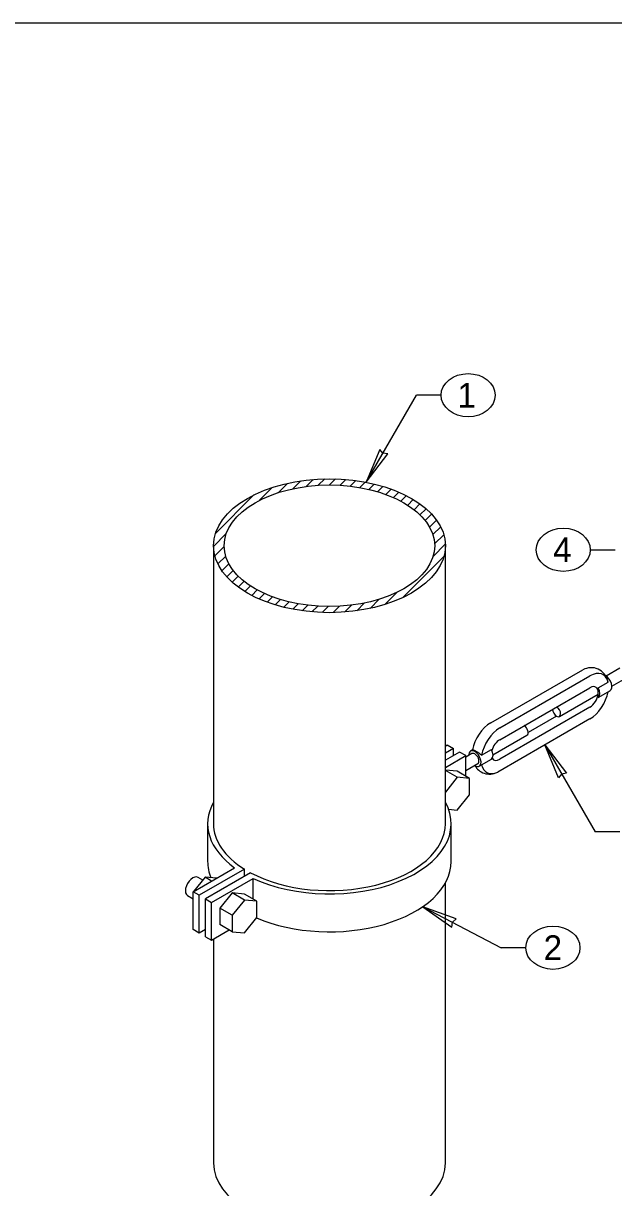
# Model space of a CAD drawing. Extents: x 99862 to 104211, y 98939 to 102076.
# Drawn here: x 101156 to 101538, y 101322 to 102076 of the extents above; entities that cross this region are included whole.
import ezdxf

# ---------------------------------------------------------------- set-up
doc = ezdxf.new("R2010")
doc.units = 0
for name, color, linetype in [('Level 1', 7, 'Continuous'), ('Level 12', 7, 'Continuous'), ('Level 15', 7, 'Continuous'), ('Level 2', 7, 'Continuous'), ('Level 20', 7, 'Continuous'), ('Level 3', 7, 'Continuous')]:
    doc.layers.add(name, color=color, linetype=linetype)

msp = doc.modelspace()

# ---------------------------------------------------------------- linework, layer by layer
at = {"layer": 'Level 1'}
for p, q in [((101279.4, 101737.55), (101279.4, 101557.76)), ((101429.4, 101557.76), (101429.4, 101737.55)), ((101429.4, 101338.36), (101429.4, 101519.41)), ((101279.4, 101483.08), (101279.4, 101338.36))]:
    msp.add_line(p, q, dxfattribs=at)
msp.add_lwpolyline([(99862, 99999.5), (103151, 99999.5), (103151, 102075.5), (99862, 102075.5)], close=True, dxfattribs=at)
for major_axis in [(75, 0), (68.07, 0)]:
    msp.add_ellipse((101354.4, 101737.55), major_axis=major_axis, ratio=0.57735, dxfattribs=at)
msp.add_ellipse((101354.4, 101338.36), major_axis=(75, 0), ratio=0.57735, start_param=3.141593, end_param=6.283185, dxfattribs=at)
at = {"layer": 'Level 12'}
for p, q in [((101309.2, 101766.94), (101317.47, 101775.21)), ((101321.19, 101771.86), (101327.22, 101777.88)), ((101330.83, 101774.42), (101335.92, 101779.51)), ((101339.36, 101775.88), (101343.87, 101780.39)), ((101347.18, 101776.63), (101351.36, 101780.81)), ((101354.47, 101776.85), (101358.39, 101780.77)), ((101361.34, 101776.64), (101365.07, 101780.38)), ((101367.84, 101776.07), (101371.45, 101779.69)), ((101374.02, 101775.18), (101377.55, 101778.72)), ((101379.89, 101773.99), (101383.38, 101777.48)), ((101385.49, 101772.51), (101388.95, 101775.97)), ((101280.73, 101745.54), (101305.61, 101770.41)), ((101390.8, 101770.75), (101394.26, 101774.21)), ((101395.84, 101768.72), (101399.32, 101772.2)), ((101400.6, 101766.41), (101404.12, 101769.93)), ((101405.06, 101763.8), (101408.66, 101767.4)), ((101409.19, 101760.86), (101412.92, 101764.59)), ((101412.97, 101757.57), (101416.89, 101761.49)), ((101416.33, 101753.85), (101420.47, 101757.99)), ((101419.17, 101749.62), (101423.65, 101754.1)), ((101279.42, 101737.16), (101287.72, 101745.45)), ((101421.32, 101744.71), (101426.35, 101749.73)), ((101421.4, 101730.65), (101429.33, 101738.57)), ((101422.43, 101738.74), (101428.34, 101744.65)), ((101280.29, 101730.95), (101286.33, 101737)), ((101282.23, 101725.83), (101287.31, 101730.9)), ((101401.87, 101704.04), (101428.38, 101730.55)), ((101284.86, 101721.38), (101289.38, 101725.91)), ((101288.01, 101717.46), (101292.17, 101721.62)), ((101291.55, 101713.93), (101295.48, 101717.86)), ((101295.47, 101710.78), (101299.22, 101714.53)), ((101299.71, 101707.95), (101303.33, 101711.57)), ((101304.23, 101705.4), (101307.76, 101708.92)), ((101390.33, 101699.57), (101398.26, 101707.5)), ((101309.01, 101703.11), (101312.49, 101706.58)), ((101314.05, 101701.07), (101317.5, 101704.52)), ((101319.33, 101699.29), (101322.79, 101702.74)), ((101324.87, 101697.75), (101328.36, 101701.24)), ((101330.67, 101696.48), (101334.21, 101700.02)), ((101372.11, 101695.49), (101377.12, 101700.51)), ((101380.72, 101697.03), (101386.62, 101702.93)), ((101336.75, 101695.49), (101340.36, 101699.1)), ((101343.1, 101694.77), (101346.83, 101698.49)), ((101349.76, 101694.36), (101353.66, 101698.25)), ((101356.75, 101694.28), (101360.91, 101698.43)), ((101364.19, 101694.64), (101368.67, 101699.13))]:
    msp.add_line(p, q, dxfattribs=at)
at = {"layer": 'Level 15'}
for p, q in [((101378.11, 101778.63), (101410.61, 101834.92)), ((101426.61, 101834.92), (101410.61, 101834.92)), ((101523.11, 101734.94), (101539.11, 101734.94)), ((101493.71, 101608.67), (101526.21, 101552.38)), ((101542.21, 101552.38), (101526.21, 101552.38)), ((101414.71, 101504.04), (101465.43, 101477.54)), ((101481.43, 101477.54), (101465.43, 101477.54))]:
    msp.add_line(p, q, dxfattribs=at)
for points in [[(101378.11, 101778.63), (101392.11, 101796.91), (101389, 101797.49), (101386.94, 101799.89)], [(101493.71, 101608.67), (101507.71, 101590.39), (101504.59, 101589.81), (101502.54, 101587.4)], [(101414.71, 101504.04), (101433.56, 101490.82), (101434.01, 101493.96), (101436.33, 101496.11)]]:
    msp.add_lwpolyline(points, close=True, dxfattribs=at)
at = {"layer": 'Level 2'}
for p, q in [((101429.4, 101607.95), (101430.63, 101608.67)), ((101434.61, 101606.37), (101429.4, 101603.36)), ((101438.59, 101604.08), (101429.4, 101598.77)), ((101430.63, 101608.67), (101434.61, 101606.37)), ((101434.61, 101601.78), (101434.61, 101606.37)), ((101442.56, 101601.78), (101438.59, 101604.08)), ((101429.4, 101594.18), (101442.56, 101601.78)), ((101442.56, 101588.53), (101442.56, 101601.78)), ((101437.1, 101591.68), (101429.4, 101592.37)), ((101437.1, 101587.8), (101429.4, 101592.25)), ((101437.1, 101587.8), (101429.4, 101578.21)), ((101445.05, 101587.09), (101437.1, 101591.68)), ((101445.05, 101587.09), (101437.1, 101587.8)), ((101445.05, 101576.48), (101445.05, 101587.09)), ((101437.1, 101566.58), (101445.05, 101576.48)), ((101431.47, 101567.09), (101437.1, 101566.58)), ((101275.65, 101557.76), (101275.65, 101533.27)), ((101433.15, 101533.27), (101433.15, 101557.76)), ((101266.23, 101513.75), (101293.06, 101529.24)), ((101299.41, 101528.32), (101270.21, 101511.45)), ((101299.41, 101523.72), (101299.41, 101528.32)), ((101273.96, 101523.14), (101266.56, 101513.94)), ((101272.45, 101521.26), (101269.43, 101523)), ((101281.35, 101522.48), (101273.96, 101523.14)), ((101278.23, 101520.68), (101273.96, 101523.14)), ((101303.39, 101526.02), (101274.18, 101509.16)), ((101278.16, 101506.86), (101305, 101522.36)), ((101305, 101509.1), (101305, 101522.36)), ((101266.23, 101489.26), (101266.23, 101513.75)), ((101270.21, 101511.45), (101266.23, 101513.75)), ((101270.21, 101486.96), (101270.21, 101511.45)), ((101291.58, 101512.97), (101283.62, 101503.07)), ((101299.53, 101512.26), (101291.58, 101512.97)), ((101299.53, 101508.37), (101291.58, 101512.97)), ((101307.49, 101507.66), (101299.53, 101512.26)), ((101262.63, 101511.22), (101266.23, 101509.14)), ((101274.18, 101484.66), (101274.18, 101509.16)), ((101274.18, 101509.16), (101278.16, 101506.86)), ((101278.16, 101482.37), (101278.16, 101506.86)), ((101299.53, 101508.37), (101291.58, 101498.48)), ((101307.49, 101507.66), (101299.53, 101508.37)), ((101307.49, 101497.06), (101307.49, 101507.66)), ((101283.62, 101503.07), (101283.62, 101492.46)), ((101291.58, 101498.48), (101283.62, 101503.07)), ((101291.58, 101498.48), (101291.58, 101487.87)), ((101299.53, 101487.16), (101307.49, 101497.06)), ((101270.21, 101486.96), (101266.23, 101489.26)), ((101274.18, 101489.26), (101270.21, 101486.96)), ((101278.16, 101482.37), (101289.64, 101488.99)), ((101291.58, 101487.87), (101283.62, 101492.46)), ((101274.18, 101484.66), (101278.16, 101482.37)), ((101291.58, 101487.87), (101299.53, 101487.16))]:
    msp.add_line(p, q, dxfattribs=at)
for centre, major_axis, start_param, end_param in [((101354.4, 101557.76), (78.75, 0), 2.831748, 3.819642), ((101354.4, 101557.76), (78.75, 0), 4.03434, 6.59303), ((101354.4, 101557.76), (75, 0), 3.141591, 3.889482), ((101354.4, 101557.76), (75, 0), 3.9645, 6.283185), ((101354.4, 101533.27), (78.75, 0), 3.141593, 3.37391), ((101354.4, 101533.27), (78.75, 0), 4.071408, 6.283185), ((101266.03, 101517.11), (-3.4, -5.89), 3.141579, 6.283185)]:
    msp.add_ellipse(centre, major_axis=major_axis, ratio=0.57735, start_param=start_param, end_param=end_param, dxfattribs=at)
at = {"layer": 'Level 20'}
for centre in [(101444.11, 101834.92), (101505.61, 101734.94), (101498.93, 101477.54)]:
    msp.add_ellipse(centre, major_axis=(-17.5, 0), ratio=0.8, dxfattribs=at)
at = {"layer": 'Level 3'}
for p, q in [((101458.7, 101623.02), (101518.34, 101657.37)), ((101542.15, 101658.25), (101533.33, 101653.16)), ((101464.54, 101619.65), (101522.87, 101653.33)), ((101528.27, 101645.66), (101534.62, 101649.32)), ((101537.08, 101646.66), (101544.65, 101651.03)), ((101464.54, 101612.03), (101522.87, 101645.72)), ((101503.17, 101627.08), (101528.26, 101641.57)), ((101528.27, 101643.42), (101528.27, 101645.66)), ((101528.27, 101639.41), (101534.62, 101643.08)), ((101528.27, 101639.41), (101528.27, 101641.65)), ((101534.62, 101643.08), (101535.92, 101643.83)), ((101522.87, 101633.12), (101464.54, 101599.44)), ((101522.87, 101625.51), (101463.22, 101591.15)), ((101501.18, 101627.33), (101482.94, 101616.8)), ((101460.19, 101602.27), (101482.16, 101614.95)), ((101446.59, 101603.08), (101442.56, 101600.75)), ((101447, 101605.48), (101445.65, 101604.7)), ((101452.8, 101602.08), (101459.14, 101605.75)), ((101442.56, 101592.09), (101450.34, 101596.58)), ((101451.28, 101594.96), (101459.14, 101599.5))]:
    msp.add_line(p, q, dxfattribs=at)
for centre, major_axis, start_param, end_param in [((101522.87, 101639.42), (8.52, 14.76), 5.724146, 7.068583), ((101533.11, 101648.7), (-2.81, 4.87), 3.141593, 5.509797), ((101522.87, 101639.42), (-3.86, -6.68), 2.215505, 3.926991), ((101522.87, 101639.42), (8.52, 14.76), 3.926991, 5.271429), ((101522.87, 101639.42), (-3.86, -6.68), 0.785398, 2.215505), ((101525.36, 101644.22), (-2.81, 4.87), 3.179406, 4.674575), ((101501.29, 101630.33), (-1.87, 3.25), 0.828451, 5.454735), ((101458.7, 101609.11), (-8.52, -14.76), 3.926991, 5.271086), ((101464.54, 101605.74), (8.52, 14.76), 0.785398, 2.129836), ((101480.29, 101618.2), (-1.87, 3.25), 3.14158, 5.454735), ((101464.54, 101605.74), (-3.86, -6.68), 3.926991, 5.124543), ((101448.47, 101599.83), (-2.81, 4.87), 6.283185, 7.124254), ((101448.47, 101599.83), (-2.81, 4.87), 2.300524, 6.283185), ((101448.47, 101599.83), (-1.87, 3.25), 3.141586, 6.283197), ((101456.22, 101604.31), (-2.81, 4.87), 3.179406, 4.674575), ((101464.54, 101605.74), (8.52, 14.76), 2.582553, 3.81706), ((101464.54, 101605.74), (-3.86, -6.68), 5.973762, 7.068583)]:
    msp.add_ellipse(centre, major_axis=major_axis, ratio=0.57735, start_param=start_param, end_param=end_param, dxfattribs=at)
for points, degree in [([(101534.48, 101650), (101533.61, 101653.4), (101528.81, 101659.39), (101521.4, 101658.81), (101518.34, 101657.37)], 3), ([(101534.62, 101649.32), (101534.58, 101649.54), (101534.54, 101649.76), (101534.48, 101650)], 2), ([(101528.27, 101643.42), (101528.27, 101643.42), (101528.27, 101643.42)], 2), ([(101447, 101605.48), (101447.27, 101605.63), (101448, 101605.4), (101449.64, 101604.46), (101450.28, 101604.03), (101451.57, 101603.09), (101452.21, 101602.59), (101452.8, 101602.08)], 3), ([(101448.51, 101595.21), (101449.73, 101593.24), (101454.06, 101589.25), (101460.16, 101589.72), (101463.22, 101591.15)], 3)]:
    msp.add_open_spline(points, degree=degree, dxfattribs=at)

# ---------------------------------------------------------------- texts
at = {"layer": 'Level 20'}
for s, p in [('1', (101437.24, 101826.92)), ('4', (101499.1, 101726.94)), ('2', (101492.94, 101469.54))]:
    msp.add_text(s, height=16, dxfattribs=at).set_placement(p)

doc.saveas('drawing.dxf')
